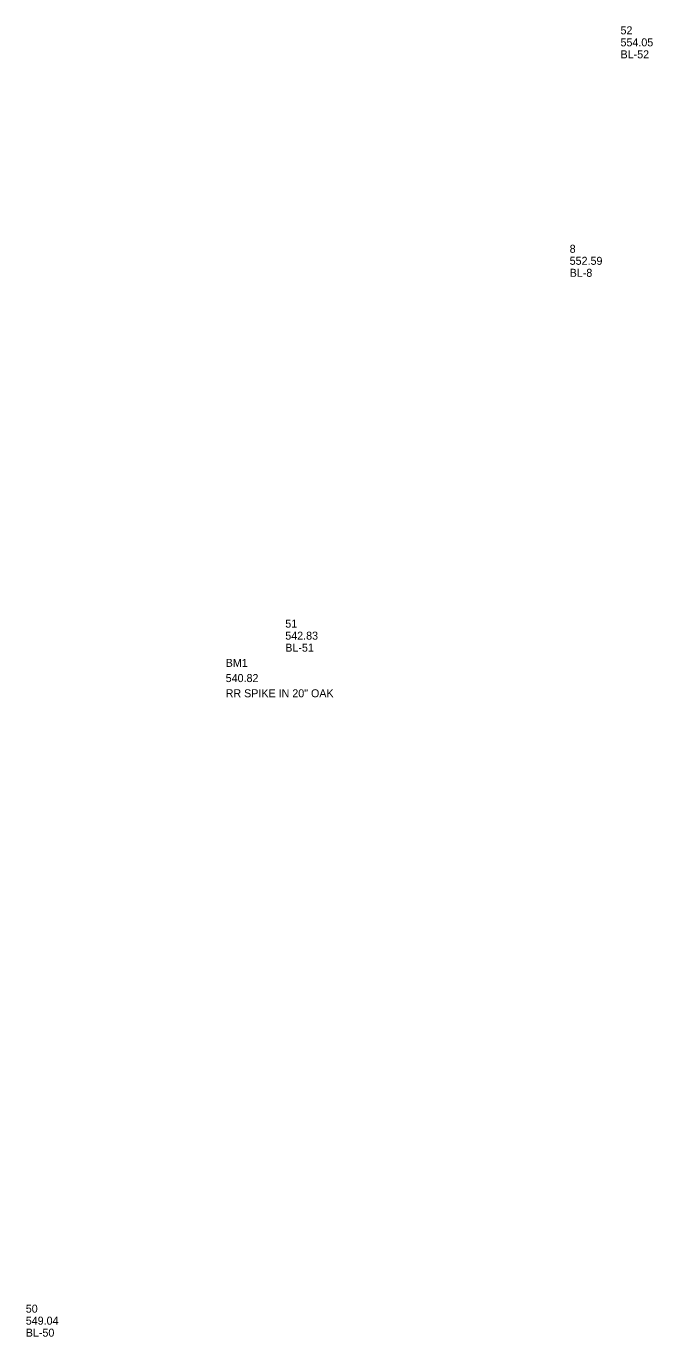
# Model space of a CAD drawing. Extents: x 1649669 to 1659218, y 588594 to 607900.
# Drawn here: x 1652239 to 1652631, y 588594 to 589412 of the extents above; entities that cross this region are included whole.
import ezdxf

# ---------------------------------------------------------------- set-up
doc = ezdxf.new("R2010")
doc.units = 0
for name, color, linetype in [('CTL Bench Mark Cogo Comment', 7, 'Continuous'), ('CTL Bench Mark Cogo Elevation', 7, 'Continuous'), ('CTL Bench Mark Cogo Number', 7, 'Continuous'), ('CTL Supplemental Horizontal and Vertical Cogo Comment', 7, 'Continuous'), ('CTL Supplemental Horizontal and Vertical Cogo Elevation', 7, 'Continuous'), ('CTL Supplemental Horizontal and Vertical Cogo Number', 7, 'Continuous')]:
    doc.layers.add(name, color=color, linetype=linetype)

msp = doc.modelspace()

# ---------------------------------------------------------------- texts
at = {"layer": 'CTL Bench Mark Cogo Comment'}
msp.add_text('RR SPIKE IN 20" OAK', height=5, dxfattribs=at).set_placement((1652363.96, 588993.3))
at = {"layer": 'CTL Bench Mark Cogo Elevation'}
msp.add_text('540.82', height=5, dxfattribs=at).set_placement((1652363.96, 589002.8))
at = {"layer": 'CTL Bench Mark Cogo Number'}
msp.add_text('BM1', height=5, dxfattribs=at).set_placement((1652363.96, 589012.3))
at = {"layer": 'CTL Supplemental Horizontal and Vertical Cogo Comment'}
for s, p in [('BL-52', (1652610.57, 589392.35)), ('BL-8', (1652578.82, 589255.91)), ('BL-51', (1652401.18, 589021.79)), ('BL-50', (1652239.08, 588593.97))]:
    msp.add_text(s, height=5, dxfattribs=at).set_placement(p)
at = {"layer": 'CTL Supplemental Horizontal and Vertical Cogo Elevation'}
for s, p in [('554.05', (1652610.57, 589399.85)), ('552.59', (1652578.82, 589263.41)), ('542.83', (1652401.18, 589029.29)), ('549.04', (1652239.08, 588601.47))]:
    msp.add_text(s, height=5, dxfattribs=at).set_placement(p)
at = {"layer": 'CTL Supplemental Horizontal and Vertical Cogo Number'}
for s, p in [('52', (1652610.57, 589407.35)), ('8', (1652578.82, 589270.91)), ('51', (1652401.18, 589036.79)), ('50', (1652239.08, 588608.97))]:
    msp.add_text(s, height=5, dxfattribs=at).set_placement(p)

doc.saveas('drawing.dxf')
